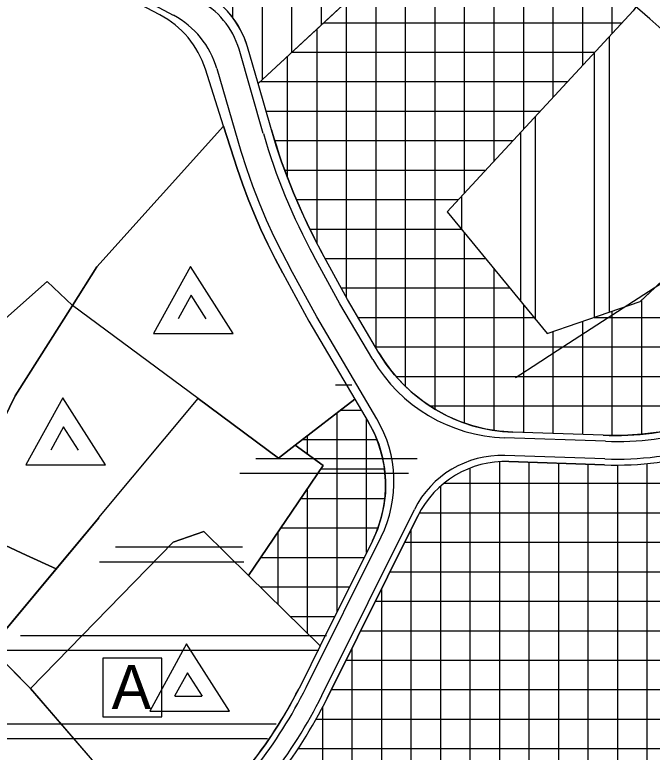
# Model space of a CAD drawing. Extents: x 427903 to 430077, y 4477233 to 4480385.
# Drawn here: x 428396.6 to 428612.6, y 4478272.2 to 4478522.4 of the extents above; entities that cross this region are included whole.
import ezdxf

# ---------------------------------------------------------------- set-up
doc = ezdxf.new("R2010")
doc.units = 0
for name, color, linetype in [('ADA', 7, 'Continuous'), ('ADAKENARI', 7, 'Continuous'), ('Default', 7, 'Continuous'), ('KALDIRIM', 7, 'Continuous'), ('PL_AYA_PARK_DINLENME', 7, 'Continuous'), ('PL_K_ASKERI_ALAN', 7, 'Continuous'), ('PL_K_TALI_IS_MRK', 7, 'Continuous'), ('PL_KON_MEV_350', 7, 'Continuous'), ('PL_SAY_ORTAOGRETIM', 7, 'Continuous'), ('S_SIT', 7, 'Continuous'), ('SIT_1_DER_ARKEOLOJIK', 7, 'Continuous'), ('TA_DERIVASYON', 7, 'Continuous'), ('TR_2_SITKORUMA', 7, 'Continuous'), ('TR_ASKERIALAN', 7, 'Continuous'), ('TR_ORTAYOGUNKONUT', 7, 'Continuous'), ('TR_TALIISMERK', 7, 'Continuous')]:
    doc.layers.add(name, color=color, linetype=linetype)

msp = doc.modelspace()

# ---------------------------------------------------------------- linework, layer by layer
at = {"layer": 'ADA'}
msp.add_line((428547.85, 4478562.97), (428479.05, 4478499.09), dxfattribs=at)
at = {"layer": 'ADAKENARI'}
for p, q in [((428606.14, 4478523.73), (428543.11, 4478455.55)), ((428479.05, 4478499.09), (428475.46, 4478511.54)), ((428467.33, 4478484.69), (428461.18, 4478503.96)), ((428483.58, 4478483.39), (428479.05, 4478499.09)), ((428467.33, 4478484.69), (428424.42, 4478436.9)), ((428471.94, 4478470.26), (428467.33, 4478484.69)), ((428473.76, 4478465.03), (428471.94, 4478470.26)), ((428475.71, 4478459.84), (428473.76, 4478465.03)), ((428477.8, 4478454.71), (428475.71, 4478459.84)), ((428480.01, 4478449.63), (428477.8, 4478454.71)), ((428543.11, 4478455.55), (428577.05, 4478414.28)), ((428482.35, 4478444.61), (428480.01, 4478449.63)), ((428484.82, 4478439.65), (428482.35, 4478444.61)), ((428509.34, 4478425.89), (428500.78, 4478441.57)), ((428487.41, 4478434.75), (428484.82, 4478439.65)), ((428424.42, 4478436.9), (428416.11, 4478423.81)), ((428487.41, 4478434.75), (428496.29, 4478418.49)), ((428608.59, 4478425.15), (428619.86, 4478435.8)), ((428416.11, 4478423.81), (428396.66, 4478393.17)), ((428458.75, 4478392.22), (428416.11, 4478423.81)), ((428520, 4478407.78), (428509.34, 4478425.89)), ((428577.05, 4478414.28), (428608.59, 4478425.15)), ((428496.29, 4478418.49), (428511.86, 4478392.05)), ((428396.66, 4478393.17), (428375.92, 4478350.49)), ((428425.1, 4478351.87), (428458.75, 4478392.22)), ((428458.75, 4478392.22), (428485.91, 4478372)), ((428491.6, 4478376.4), (428511.86, 4478392.05)), ((428511.86, 4478392.05), (428516.39, 4478384.35)), ((428595.99, 4478379.77), (428565.34, 4478380.82)), ((428485.91, 4478372), (428491.6, 4478376.4)), ((428491.6, 4478376.4), (428501.06, 4478369.51)), ((428501.06, 4478369.51), (428475.83, 4478332.21)), ((428564.03, 4478370.86), (428596.49, 4478369.75)), ((428425.09, 4478351.81), (428388.27, 4478307.62)), ((428502.46, 4478290.6), (428533.2, 4478352.48)), ((428460.7, 4478347.09), (428450.27, 4478343.57)), ((428475.83, 4478332.21), (428460.7, 4478347.09)), ((428517.83, 4478344.01), (428500.11, 4478308.34)), ((428450.27, 4478343.57), (428401.88, 4478293.84)), ((428500.11, 4478308.34), (428475.83, 4478332.21)), ((428388.27, 4478307.62), (428401.88, 4478293.84)), ((428500.11, 4478308.34), (428493.72, 4478295.48)), ((428401.88, 4478293.84), (428448.29, 4478240.18))]:
    msp.add_line(p, q, dxfattribs=at)
for points in [[(428292.85, 4478330.03), (428407.55, 4478431.91), (428416.11, 4478423.81)], [(428375.92, 4478350.49), (428384.62, 4478346.46), (428400.38, 4478339.16), (428410.61, 4478334.42)]]:
    msp.add_lwpolyline(points, dxfattribs=at)
for centre, radius, start, end in [((428446.63, 4478503.23), 30, 16.0868, 63.6718), ((428430.7, 4478494.22), 32, 17.7146, 61.8633), ((428682.36, 4478540.72), 206.88, 196.0868, 208.6367), ((428567.22, 4478435.59), 54.8, 210.4929, 268.033), ((428599.58, 4478484.28), 104.57, 268.033, 304.4016), ((428600.34, 4478481.68), 112, 268.033, 304.4016), ((428479.89, 4478362.86), 42.36, 333.5849, 30.4929), ((428562.89, 4478337.74), 33.15, 88.033, 153.5849), ((428352.81, 4478365.48), 157.34, 310.1715, 333.5849), ((428354.69, 4478364), 164.99, 310.1715, 333.5849)]:
    msp.add_arc(centre, radius, start, end, dxfattribs=at)
at = {"layer": 'Default'}
for p, q in [((428456.09, 4478437.09), (428443.54, 4478414.28)), ((428470.56, 4478414.28), (428456.09, 4478437.09)), ((428456.39, 4478427.27), (428452, 4478419.28)), ((428461.47, 4478419.28), (428456.39, 4478427.27)), ((428443.54, 4478414.28), (428470.56, 4478414.28)), ((428412.83, 4478392.52), (428400.29, 4478369.7)), ((428427.31, 4478369.7), (428412.83, 4478392.52)), ((428413.14, 4478382.7), (428408.74, 4478374.7)), ((428418.21, 4478374.7), (428413.14, 4478382.7)), ((428400.29, 4478369.7), (428427.31, 4478369.7)), ((428454.83, 4478309.05), (428442.29, 4478286.24)), ((428469.31, 4478286.24), (428454.83, 4478309.05)), ((428455.14, 4478299.23), (428450.74, 4478291.24)), ((428460.21, 4478291.24), (428455.14, 4478299.23)), ((428450.81, 4478291.24), (428460.02, 4478291.24)), ((428442.29, 4478286.24), (428469.31, 4478286.24))]:
    msp.add_line(p, q, dxfattribs=at)
at = {"layer": 'KALDIRIM'}
for p, q in [((428450.4, 4478522.24), (428357.59, 4478571.87)), ((428480.81, 4478482.15), (428472.57, 4478510.71)), ((428465.05, 4478504.17), (428473.2, 4478476.19)), ((428473.2, 4478476.19), (428475.1, 4478470.28)), ((428475.1, 4478470.28), (428477.18, 4478464.42)), ((428477.18, 4478464.42), (428479.42, 4478458.63)), ((428479.42, 4478458.63), (428481.83, 4478452.91)), ((428481.83, 4478452.91), (428484.41, 4478447.26)), ((428484.41, 4478447.26), (428487.15, 4478441.68)), ((428487.15, 4478441.68), (428490.04, 4478436.19)), ((428506.73, 4478424.41), (428497.94, 4478440.5)), ((428498.9, 4478419.97), (428490.04, 4478436.19)), ((428517.88, 4478405.48), (428506.73, 4478424.41)), ((428519.3, 4478385.33), (428498.9, 4478419.97)), ((428596.77, 4478377.74), (428562.55, 4478378.92)), ((428596.56, 4478371.75), (428562.71, 4478372.91)), ((428500.67, 4478291.49), (428532.03, 4478354.61)), ((428495.3, 4478294.16), (428520.72, 4478345.34))]:
    msp.add_line(p, q, dxfattribs=at)
for centre, radius, start, end in [((428446.63, 4478503.23), 27, 16.0868, 63.6718), ((428436.25, 4478495.79), 30, 16.2237, 61.8633), ((428678.74, 4478539.23), 205.99, 196.0868, 208.6367), ((428564.41, 4478432.88), 54, 210.4929, 268.033), ((428600.34, 4478481.68), 104, 268.033, 304.4016), ((428600.34, 4478481.68), 110, 268.033, 304.4016), ((428483.11, 4478364.02), 42, 333.5849, 30.4929), ((428561.58, 4478339.93), 33, 88.033, 153.5849), ((428354.69, 4478364), 156.99, 310.1715, 333.5849), ((428354.69, 4478364), 162.99, 310.1715, 333.5849)]:
    msp.add_arc(centre, radius, start, end, dxfattribs=at)
at = {"layer": 'PL_AYA_PARK_DINLENME'}
msp.add_lwpolyline([(428501.06, 4478369.51), (428475.83, 4478332.21), (428460.7, 4478347.09), (428450.27, 4478343.57), (428401.88, 4478293.84), (428388.27, 4478307.62), (428425.09, 4478351.81), (428425.1, 4478351.87), (428458.75, 4478392.22), (428485.91, 4478372), (428491.6, 4478376.4)], close=True, dxfattribs=at)
at = {"layer": 'PL_K_ASKERI_ALAN'}
msp.add_lwpolyline([(428652.94, 4478589.44), (428606.14, 4478523.73), (428543.11, 4478455.55), (428577.05, 4478414.28), (428608.59, 4478425.15), (428619.86, 4478435.8), (428690.39, 4478531.86)], dxfattribs=at)
at = {"layer": 'PL_K_TALI_IS_MRK'}
for points in [[(428615.83, 4478380.98), (428609.25, 4478380.16), (428602.62, 4478379.75), (428595.99, 4478379.77), (428565.34, 4478380.82), (428560.77, 4478381.17), (428556.25, 4478381.9), (428551.8, 4478383.01), (428547.45, 4478384.48), (428543.25, 4478386.31), (428539.22, 4478388.49), (428535.38, 4478391), (428531.76, 4478393.81), (428528.39, 4478396.92), (428525.3, 4478400.31), (428522.49, 4478403.93), (428520, 4478407.78), (428509.34, 4478425.89), (428500.78, 4478441.57), (428498.13, 4478446.57), (428495.63, 4478451.65), (428493.26, 4478456.8), (428491.03, 4478462.01), (428488.95, 4478467.27), (428487.01, 4478472.6), (428485.22, 4478477.97), (428483.58, 4478483.39), (428479.05, 4478499.09), (428547.85, 4478562.97)], [(428606.14, 4478523.73), (428543.11, 4478455.55), (428577.05, 4478414.28), (428608.59, 4478425.15), (428619.86, 4478435.8)], [(428292.85, 4478330.03), (428296.45, 4478310.42), (428277.1, 4478309.36), (428274.62, 4478211.7), (428341.4, 4478178.64), (428344.62, 4478173.77), (428347.68, 4478169.16), (428402.49, 4478201.51), (428448.29, 4478240.18), (428401.88, 4478293.84), (428388.27, 4478307.62), (428410.61, 4478334.42), (428400.38, 4478339.16), (428384.62, 4478346.46), (428375.92, 4478350.49), (428396.66, 4478393.17), (428416.11, 4478423.81), (428407.55, 4478431.91), (428292.85, 4478330.03)], [(428596.49, 4478369.75), (428564.03, 4478370.86)], [(428533.2, 4478352.48), (428502.46, 4478290.6)]]:
    msp.add_lwpolyline(points, dxfattribs=at)
msp.add_lwpolyline([(428516.39, 4478384.35), (428518.35, 4478380.63), (428519.92, 4478376.73), (428521.1, 4478372.69), (428521.87, 4478368.56), (428522.23, 4478364.37), (428522.17, 4478360.16), (428521.69, 4478355.98), (428520.8, 4478351.87), (428519.51, 4478347.87), (428517.83, 4478344.01), (428500.11, 4478308.34), (428475.83, 4478332.21), (428501.06, 4478369.51), (428491.6, 4478376.4), (428511.86, 4478392.05)], close=True, dxfattribs=at)
for centre, radius, start, end in [((428600.34, 4478481.68), 112, 268.033, 304.4016), ((428562.89, 4478337.74), 33.15, 88.033, 153.5849), ((428354.69, 4478364), 164.99, 310.1715, 333.5849)]:
    msp.add_arc(centre, radius, start, end, dxfattribs=at)
at = {"layer": 'PL_KON_MEV_350'}
for points in [[(428445.79, 4478522.44), (428419.11, 4478536.59), (428364.08, 4478566.14), (428356.73, 4478538.73), (428347.48, 4478504.21), (428346.73, 4478503.43), (428336.73, 4478492.99), (428331.05, 4478487.06), (428326.73, 4478480.12), (428318.4, 4478466.76), (428316.73, 4478461.32), (428311.62, 4478444.67), (428306.73, 4478434.84), (428296.73, 4478414.73), (428286.73, 4478394.62)], [(428547.85, 4478562.97), (428479.05, 4478499.09), (428475.46, 4478511.54), (428474.44, 4478514.49), (428473.12, 4478517.31), (428471.52, 4478519.98), (428469.65, 4478522.47)], [(428286.73, 4478394.62), (428276.73, 4478374.51), (428275.98, 4478373), (428266.73, 4478364.67), (428256.73, 4478355.67), (428250.5, 4478350.05), (428256.73, 4478331.29), (428258.58, 4478325.75), (428290.41, 4478343.36), (428292.85, 4478330.03), (428407.55, 4478431.91), (428416.11, 4478423.81), (428424.42, 4478436.9), (428467.33, 4478484.69), (428461.18, 4478503.96)]]:
    msp.add_lwpolyline(points, dxfattribs=at)
msp.add_arc((428430.7, 4478494.22), 32, 17.7146, 61.8633, dxfattribs=at)
at = {"layer": 'PL_SAY_ORTAOGRETIM'}
for points in [[(428487.41, 4478434.75), (428496.29, 4478418.49), (428511.86, 4478392.05), (428491.6, 4478376.4), (428485.91, 4478372), (428458.75, 4478392.22), (428416.11, 4478423.81), (428424.42, 4478436.9), (428467.33, 4478484.69), (428471.94, 4478470.26), (428473.76, 4478465.03), (428475.71, 4478459.84), (428477.8, 4478454.71), (428480.01, 4478449.63), (428482.35, 4478444.61), (428484.82, 4478439.65)], [(428475.83, 4478332.21), (428500.11, 4478308.34), (428493.72, 4478295.48), (428489.96, 4478288.38), (428485.85, 4478281.48), (428481.39, 4478274.79), (428476.59, 4478268.35), (428471.47, 4478262.15), (428466.04, 4478256.23), (428460.31, 4478250.59), (428454.31, 4478245.25), (428448.29, 4478240.18), (428401.88, 4478293.84), (428450.27, 4478343.57), (428460.7, 4478347.09)]]:
    msp.add_lwpolyline(points, close=True, dxfattribs=at)
msp.add_lwpolyline([(428410.61, 4478334.42), (428425.09, 4478351.81), (428425.1, 4478351.87), (428458.75, 4478392.22), (428416.11, 4478423.81), (428396.66, 4478393.17), (428375.92, 4478350.49), (428384.62, 4478346.46), (428400.38, 4478339.16), (428410.61, 4478334.42)], dxfattribs=at)
at = {"layer": 'S_SIT'}
for p, q in [((428446.45, 4478304.22), (428426.45, 4478304.22)), ((428426.45, 4478304.22), (428426.45, 4478284.22)), ((428446.45, 4478284.22), (428446.45, 4478304.22)), ((428426.45, 4478284.22), (428446.45, 4478284.22))]:
    msp.add_line(p, q, dxfattribs=at)
at = {"layer": 'SIT_1_DER_ARKEOLOJIK'}
msp.add_lwpolyline([(428631.11, 4478503.82), (428611.76, 4478521.09), (428605.96, 4478526.19)], dxfattribs=at)
at = {"layer": 'TA_DERIVASYON'}
msp.add_lwpolyline([(428566.32, 4478399.37), (428566.54, 4478399.52), (428568.08, 4478400.52), (428572.26, 4478403.23), (428580.41, 4478408.52), (428593.84, 4478417.24), (428613.32, 4478429.83), (428637.31, 4478445.08), (428663.74, 4478461.36), (428690.52, 4478477.02), (428715.56, 4478490.45), (428737.4, 4478500.38), (428757.13, 4478506.99), (428776.43, 4478510.84), (428797.01, 4478512.5), (428820.57, 4478512.52), (428848.22, 4478511.43), (428878.65, 4478509.6), (428909.96, 4478507.39), (428940.28, 4478505.16), (428967.69, 4478503.25), (428990.82, 4478502.04)], dxfattribs=at)
msp.add_lwpolyline([(428566.32, 4478399.37), (428566.54, 4478399.52), (428568.08, 4478400.52), (428572.26, 4478403.23), (428580.41, 4478408.52), (428593.84, 4478417.24), (428613.32, 4478429.83), (428637.31, 4478445.08), (428663.74, 4478461.36), (428690.52, 4478477.02), (428715.56, 4478490.45), (428737.4, 4478500.38), (428757.13, 4478506.99), (428776.43, 4478510.84), (428797.01, 4478512.5), (428820.57, 4478512.52), (428848.22, 4478511.43), (428878.65, 4478509.6), (428909.96, 4478507.39), (428940.28, 4478505.16), (428967.69, 4478503.25), (428990.82, 4478502.04)], dxfattribs=at)
at = {"layer": 'TR_2_SITKORUMA'}
for p, q in [((428505.3, 4478396.9), (428510.85, 4478396.9)), ((428478.25, 4478371.9), (428532.95, 4478371.9)), ((428472.84, 4478366.9), (428530.07, 4478366.9)), ((428430.69, 4478341.9), (428473.79, 4478341.9)), ((428425.28, 4478336.9), (428474.25, 4478336.9)), ((428398.52, 4478311.9), (428502.21, 4478311.9)), ((428393.65, 4478306.9), (428499.66, 4478306.9)), ((428370.41, 4478281.9), (428485.2, 4478281.9)), ((428366, 4478276.9), (428482.25, 4478276.9))]:
    msp.add_line(p, q, dxfattribs=at)
at = {"layer": 'TR_ASKERIALAN'}
for p, q in [((428598.11, 4478421.54), (428598.11, 4478515.04)), ((428593.11, 4478419.81), (428593.11, 4478509.63)), ((428573.11, 4478419.08), (428573.11, 4478488)), ((428568.11, 4478425.16), (428568.11, 4478482.59)), ((428548.11, 4478449.47), (428548.11, 4478460.96))]:
    msp.add_line(p, q, dxfattribs=at)
at = {"layer": 'TR_ORTAYOGUNKONUT'}
for p, q in [((428470.51, 4478521.32), (428470.51, 4478560.78)), ((428480.51, 4478500.44), (428480.51, 4478552.77)), ((428500.51, 4478519.02), (428500.51, 4478552.67)), ((428490.51, 4478509.73), (428490.51, 4478550.63)), ((428505.83, 4478365.66), (428505.83, 4478387.39)), ((428515.83, 4478359.96), (428515.83, 4478385.31)), ((428495.83, 4478373.32), (428495.83, 4478379.67)), ((428495.83, 4478312.54), (428495.83, 4478316.85))]:
    msp.add_line(p, q, dxfattribs=at)
for points in [[(428445.79, 4478522.44), (428419.11, 4478536.59), (428364.08, 4478566.14), (428356.73, 4478538.73), (428347.48, 4478504.21), (428346.73, 4478503.43), (428336.73, 4478492.99), (428331.05, 4478487.06), (428326.73, 4478480.12), (428318.4, 4478466.76), (428316.73, 4478461.32), (428311.62, 4478444.67), (428306.73, 4478434.84), (428296.73, 4478414.73), (428286.73, 4478394.62), (428276.73, 4478374.51), (428275.98, 4478373), (428266.73, 4478364.67)], [(428266.73, 4478364.67), (428256.73, 4478355.67), (428250.5, 4478350.05), (428256.73, 4478331.29), (428258.58, 4478325.75), (428290.41, 4478343.36), (428292.85, 4478330.03), (428407.55, 4478431.91), (428416.11, 4478423.81), (428424.42, 4478436.9), (428467.33, 4478484.69), (428461.18, 4478503.96)]]:
    msp.add_lwpolyline(points, dxfattribs=at)
msp.add_arc((428430.7, 4478494.22), 32, 17.7146, 61.8633, dxfattribs=at)
at = {"layer": 'TR_TALIISMERK'}
for p, q in [((428549.05, 4478461.98), (428549.05, 4478562.16)), ((428539.05, 4478388.6), (428539.05, 4478554.8)), ((428559.05, 4478472.8), (428559.05, 4478555.43)), ((428569.05, 4478483.61), (428569.05, 4478548.7)), ((428529.05, 4478396.32), (428529.05, 4478545.52)), ((428579.05, 4478494.43), (428579.05, 4478541.97)), ((428519.05, 4478409.4), (428519.05, 4478536.23)), ((428589.05, 4478505.24), (428589.05, 4478535.24)), ((428509.05, 4478426.43), (428509.05, 4478526.94)), ((428599.05, 4478516.06), (428599.05, 4478528.5)), ((428501.31, 4478519.75), (428602.46, 4478519.75)), ((428499.05, 4478444.84), (428499.05, 4478517.66)), ((428490.54, 4478509.75), (428593.22, 4478509.75)), ((428489.05, 4478467.02), (428489.05, 4478508.37)), ((428479.77, 4478499.75), (428583.97, 4478499.75)), ((428481.74, 4478489.75), (428574.73, 4478489.75)), ((428484.68, 4478479.75), (428565.48, 4478479.75)), ((428488.05, 4478469.75), (428556.24, 4478469.75)), ((428491.99, 4478459.75), (428546.99, 4478459.75)), ((428496.56, 4478449.75), (428547.87, 4478449.75)), ((428549.05, 4478383.94), (428549.05, 4478448.33)), ((428501.77, 4478439.75), (428556.1, 4478439.75)), ((428559.05, 4478381.45), (428559.05, 4478436.17)), ((428507.23, 4478429.75), (428564.32, 4478429.75)), ((428569.05, 4478380.7), (428569.05, 4478424.01)), ((428609.05, 4478380.15), (428609.05, 4478425.58)), ((428599.05, 4478379.76), (428599.05, 4478421.86)), ((428512.95, 4478419.75), (428572.55, 4478419.75)), ((428592.94, 4478419.75), (428690.43, 4478419.75)), ((428589.05, 4478380.01), (428589.05, 4478418.41)), ((428579.05, 4478380.35), (428579.05, 4478414.97)), ((428518.84, 4478409.75), (428675.83, 4478409.75)), ((428525.8, 4478399.75), (428661.22, 4478399.75)), ((428537.28, 4478389.75), (428644.17, 4478389.75)), ((428505.83, 4478319.86), (428505.83, 4478387.39)), ((428507.05, 4478388.34), (428514.05, 4478388.34)), ((428515.83, 4478339.99), (428515.83, 4478385.31)), ((428495.83, 4478373.32), (428495.83, 4478379.67)), ((428494.11, 4478378.34), (428519.27, 4478378.34)), ((428560.94, 4478160.09), (428560.94, 4478370.79)), ((428570.94, 4478170.85), (428570.94, 4478370.63)), ((428580.94, 4478182), (428580.94, 4478370.28)), ((428590.94, 4478193.16), (428590.94, 4478369.94)), ((428600.94, 4478204.31), (428600.94, 4478369.72)), ((428610.94, 4478213.8), (428610.94, 4478370.22)), ((428500.27, 4478368.34), (428521.89, 4478368.34)), ((428550.94, 4478150.44), (428550.94, 4478368.6)), ((428495.83, 4478312.54), (428495.83, 4478361.78)), ((428540.94, 4478149.31), (428540.94, 4478362.51)), ((428542.07, 4478363.48), (428812.66, 4478363.48)), ((428493.5, 4478358.34), (428521.96, 4478358.34)), ((428533.77, 4478353.48), (428798.1, 4478353.48)), ((428485.83, 4478322.38), (428485.83, 4478346.99)), ((428486.74, 4478348.34), (428519.66, 4478348.34)), ((428530.94, 4478156.96), (428530.94, 4478347.93)), ((428528.73, 4478343.48), (428783.54, 4478343.48)), ((428479.97, 4478338.34), (428515.01, 4478338.34)), ((428523.76, 4478333.48), (428725.76, 4478333.48)), ((428479.77, 4478328.34), (428510.04, 4478328.34)), ((428520.94, 4478152.78), (428520.94, 4478327.8)), ((428518.79, 4478323.48), (428722.53, 4478323.48)), ((428489.94, 4478318.34), (428505.07, 4478318.34)), ((428513.83, 4478313.48), (428718.82, 4478313.48)), ((428510.94, 4478157.6), (428510.94, 4478307.67)), ((428508.86, 4478303.48), (428708.31, 4478303.48)), ((428503.89, 4478293.48), (428695.71, 4478293.48)), ((428500.94, 4478151.3), (428500.94, 4478287.72)), ((428498.69, 4478283.48), (428686.57, 4478283.48)), ((428492.58, 4478273.48), (428676.32, 4478273.48))]:
    msp.add_line(p, q, dxfattribs=at)
msp.add_lwpolyline([(428388.27, 4478307.62), (428410.61, 4478334.42), (428400.38, 4478339.16), (428384.62, 4478346.46), (428375.92, 4478350.49), (428396.66, 4478393.17), (428416.11, 4478423.81), (428407.55, 4478431.91), (428292.85, 4478330.03), (428296.45, 4478310.42), (428277.1, 4478309.36), (428274.62, 4478211.7), (428341.4, 4478178.64), (428344.62, 4478173.77), (428347.68, 4478169.16), (428402.49, 4478201.51), (428448.29, 4478240.18), (428401.88, 4478293.84), (428388.27, 4478307.62)], dxfattribs=at)

# ---------------------------------------------------------------- texts
at = {"layer": 'S_SIT'}
msp.add_text('A', height=15, dxfattribs=at).set_placement((428429.39, 4478286.9))

doc.saveas('drawing.dxf')
